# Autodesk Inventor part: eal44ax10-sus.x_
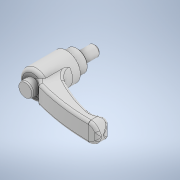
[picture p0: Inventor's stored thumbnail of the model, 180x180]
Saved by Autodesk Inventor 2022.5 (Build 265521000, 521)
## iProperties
Created: 2023-06
Part Number: eal44ax10-sus.x_
Material: Generic
Document SubType Name: Modeling
Designer: ImaoCorp
Density: 1 g/cm^3
Appearance: Default
Sending System: SOLIDWORKS 2021-2021301
MC: AMD64
MC_MODEL: Intel64 Family 6 Model 60 Stepping 3, GenuineIntel
OS: Windows_NT
FRU: Parasolid Version 32.1, build 255,  1- 1-2021
FORMAT: text
GUISE: transmit
KEY: eal44ax10-sus
FILE: eal44ax10-sus.x_t
DATE: Thu Jun 15 16:07:08 2023
Author: ImaoCorp
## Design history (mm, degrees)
feature "Base1"
node "ソリッド1"
